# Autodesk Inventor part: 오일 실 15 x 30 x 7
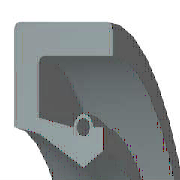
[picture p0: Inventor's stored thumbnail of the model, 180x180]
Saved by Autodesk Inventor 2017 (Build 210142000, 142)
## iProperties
Created: 2012-02
Part Number: 오일 실 15 x 30 x 7
Material: 고무
Description: 오일-실
Document SubType Name: Modeling
Standard: KS B 2804
Designer: mduedu
Standards Organization: KS
Language: ko-KR
Size Designation: S - 15 25 7
Categories: <MemberInstance><Categories><Category DisplayName="샤프트 부품" InternalName="7f7aeb1f-a693-4053-b835-cee3144e0d98" Mnemonic="SHFT"><Category DisplayName="실링" Intern
Density: 0.93 g/cm^3
Appearance: 고무 - 검은색 - 버전 1.1
IsCustomPart: 1
Author: mduedu
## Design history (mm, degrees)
revolve "본체" stored, may be unused: angle "d17" = 90 deg
revolve "스프링1" stored, may be unused: angle "d18" = 90 deg
body "Solid1"
sketch "스케치1"
  geometry: L1 (0, 15)-(7, 15); L2 (7, 15)-(7, 13.75); L3 (7, 13.75)-(1.75, 13.75); L4 (0, 15)-(0, 9.6); L5 (0, 9.6)-(1.75, 9.25); L6 (1.75, 9.25)-(4.9, 7.5); L7 (4.9, 7.5)-(0, 7.5); L8 (6.3, 8.375)-(6.3, 9.6); L9 (0, 0)-(9.586, 0) reference; L10 (4.9, 7.5)-(6.3, 8.375); L11 (0, 15)-(0, -2.5) reference; L12 (-1.917, 0)-(11.503, 0) reference; L13 (4.2, 9.6)-(1.75, 10.09); L14 (1.75, 10.09)-(1.75, 13.75); L15 (6.3, 9.6)-(5.6, 9.6); C1 r 0.455 at (4.9, 9.6); A1 r 0.7 centre (4.9, 9.6) between (5.6, 9.6) and (4.2, 9.6)
  constraints: 26 end point, 5 horizontal alignment, 4 perpendicular, 2 centre point, 2 collinear, 2 horizontal, 2 parallel, 2 point on circle, 2 point on line, 2 vertical alignment, 1 coincident
  dimensions: "d0" = 30 diameter of L1 L9 (= SD2); "d1" = 16.75 diameter of L8.start L9 (= ABDM); "d2" = 1.25 distance of L1.end L2.end (computed from SD); "d3" = 0.91 diameter of C1 (= SPDI); "d4" = 1.4 diameter of A1 (= SPDA); "d5" = 15 diameter of L6.end L9 (= NND); "d6" = 18.5 diameter of L5.end L9 (= TKDM); "d7" = 19.2 diameter of L4.end L9 (= HLDM); "d8" = 4.9 distance from line of C1.centre L4 (= SPDST); "d9" = 6.3 distance between parallel lines of L8 L4 (= SDI); "d10" = 7 distance between parallel lines of L2 L4 (= SWDT); "d12" = 1.75 distance between parallel lines of L14 L4 (= SD)
fillet "모깎기1" dims "d11" = 0.5 (= RR)
other parameters: "SD2" = 30 [user parameter; used in 1 equation term], "SWDT" = 7 [user parameter; used in 1 equation term], "RR" = 0.5 [user parameter; used in 1 equation term], "SD" = 1.75 [user parameter; used in 2 equation terms], "NND" = 15 [user parameter; used in 1 equation term], "SPDA" = 1.4 [user parameter; used in 1 equation term], "SPDI" = 0.91 [user parameter; used in 1 equation term], "TKDM" = 18.5 [user parameter; used in 1 equation term], "HLDM" = 19.2 [user parameter; used in 1 equation term], "ABDM" = 16.75 [user parameter; used in 1 equation term], "SDI" = 6.3 [user parameter; used in 1 equation term], "SPDST" = 4.9 [user parameter; used in 1 equation term], "d13" = 0, "d14" = 0, "d15" = 0, "LAB" = 0.35 [user parameter]
